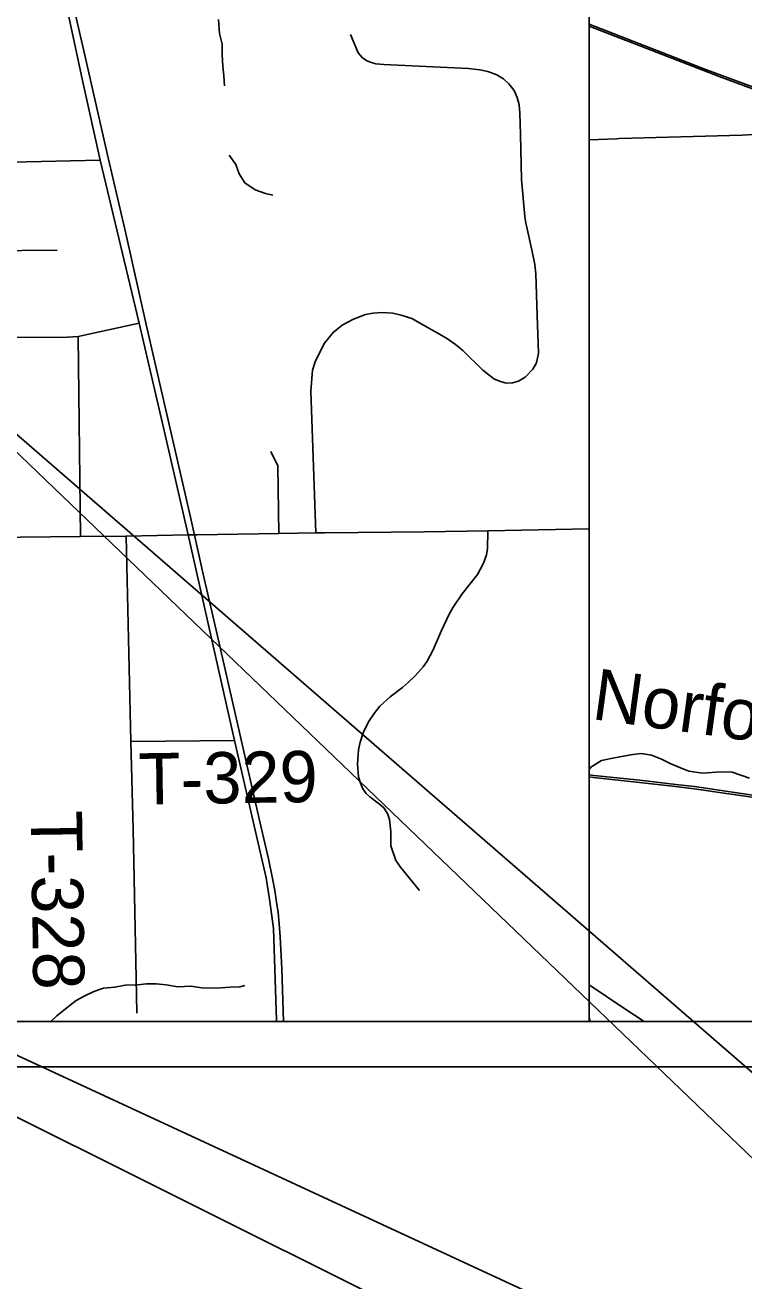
# Model space of a CAD drawing. Extents: x 25.6 to 80.6, y 0.2 to 24.5.
# Drawn here: x 43.163 to 44.756, y 13.756 to 16.537 of the extents above; entities that cross this region are included whole.
import ezdxf

# ---------------------------------------------------------------- set-up
doc = ezdxf.new("R2010")
doc.units = 0
for name, color, linetype in [('GM_X_County_Road', 7, 'Continuous'), ('GM_X_Minor_River', 7, 'Continuous'), ('GM_X_Rail_Line', 7, 'Continuous'), ('GM_X_Rail_Line_Text', 7, 'Continuous'), ('GM_X_State_Route', 7, 'Continuous'), ('GM_X_Township_Road', 7, 'Continuous'), ('GM_X_Township_Road_Text', 7, 'Continuous'), ('GM_X_US_Route', 7, 'Continuous'), ('SH_Data', 7, 'Continuous'), ('SH_Text', 7, 'Continuous')]:
    doc.layers.add(name, color=color, linetype=linetype)

msp = doc.modelspace()

# ---------------------------------------------------------------- linework, layer by layer
at = {"layer": 'GM_X_County_Road'}
for p, q in [((44.4128, 16.2831), (44.4744, 16.2855)), ((43.5241, 15.4082), (43.4744, 15.6231))]:
    msp.add_line(p, q, dxfattribs=at)
for points in [[(43.4744, 15.6231), (43.4157, 15.8771), (43.3295, 16.2378), (43.2913, 16.4079), (43.2182, 16.7492), (43.2068, 16.8496), (43.2038, 16.9808), (43.2018, 17.1076), (43.1983, 17.2332), (43.1967, 17.3603), (43.1924, 17.511), (43.1904, 17.6677), (43.19, 17.6872)], [(44.4744, 16.2855), (44.4803, 16.2858), (44.7518, 16.2938)], [(44.7518, 16.2938), (44.7637, 16.2941), (44.9482, 16.2948), (44.9691, 16.2966)], [(43.7204, 14.3303), (43.7203, 14.3334), (43.7134, 14.5361), (43.7054, 14.5964), (43.6968, 14.6488), (43.627, 14.9528), (43.5241, 15.4082)], [(44.5345, 14.3303), (44.4916, 14.3587), (44.4128, 14.4115)]]:
    msp.add_lwpolyline(points, dxfattribs=at)
at = {"layer": 'GM_X_Minor_River'}
for points in [[(43.5916, 16.5497), (43.5935, 16.5186), (43.5992, 16.4951), (43.5996, 16.4716), (43.6007, 16.4465), (43.6033, 16.4246), (43.6044, 16.4025)], [(43.615, 16.2493), (43.6297, 16.2282), (43.6369, 16.2078), (43.65, 16.1883), (43.673, 16.1726), (43.6959, 16.1646), (43.7118, 16.161)], [(44.7046, 14.8831), (44.6637, 14.8804), (44.634, 14.8847), (44.6149, 14.8921), (44.5921, 14.9017), (44.573, 14.9114), (44.5509, 14.9203), (44.5288, 14.9238), (44.5099, 14.9221), (44.4886, 14.9181), (44.4652, 14.914), (44.4402, 14.9085), (44.4168, 14.8938), (44.4128, 14.8885)], [(44.7046, 14.8831), (44.7297, 14.8827), (44.7487, 14.8762), (44.7685, 14.8696)], [(43.2198, 14.3303), (43.2331, 14.3431), (43.2526, 14.3586), (43.2758, 14.3772), (43.2953, 14.3873), (43.3149, 14.3967), (43.3367, 14.4046), (43.3617, 14.4064), (43.3844, 14.4106), (43.4124, 14.4117), (43.4321, 14.4135), (43.4533, 14.4138), (43.4753, 14.4118), (43.5011, 14.4069), (43.5306, 14.4088), (43.5534, 14.4053), (43.5731, 14.4041), (43.5966, 14.4051), (43.617, 14.4062), (43.639, 14.4073), (43.6496, 14.4104)]]:
    msp.add_lwpolyline(points, dxfattribs=at)
at = {"layer": 'GM_X_Rail_Line'}
for points in [[(43.7355, 14.3303), (43.7315, 14.4468), (43.7297, 14.4902), (43.7278, 14.5176), (43.726, 14.5466), (43.7237, 14.5715), (43.7203, 14.5945), (43.7161, 14.6203), (43.7114, 14.6473), (43.7025, 14.6906), (43.6834, 14.7698), (43.5909, 15.1777), (43.5577, 15.3212), (43.5292, 15.4472), (43.4312, 15.8739), (43.3858, 16.0756), (43.3445, 16.2531), (43.2951, 16.4705), (43.2554, 16.6435)], [(47.8128, 15.8191), (47.6057, 15.8302), (47.3402, 15.8521), (47.1631, 15.8871), (46.9912, 15.9223), (46.7273, 15.9853), (45.9383, 16.1769), (45.6136, 16.2567), (45.5036, 16.2842), (45.3992, 16.2924), (45.0499, 16.3176), (44.9789, 16.3252), (44.6728, 16.4383), (44.4128, 16.5397)], [(44.4128, 14.8771), (44.4231, 14.8756), (44.5249, 14.8648), (44.6048, 14.8557), (44.6465, 14.8507), (44.805, 14.8274), (45.0669, 14.7959), (45.2891, 14.7633), (46.0102, 14.6483), (46.3148, 14.5918), (46.4227, 14.5651), (46.528, 14.5372), (46.6857, 14.4857), (46.9234, 14.4078), (47.0403, 14.372), (47.1373, 14.3511), (47.2255, 14.3378), (47.2936, 14.3374), (47.3809, 14.3425), (47.4529, 14.3573), (47.553, 14.386), (47.7232, 14.4468), (47.8128, 14.4801)], [(44.4128, 14.8724), (44.4226, 14.871), (44.5243, 14.8601), (44.6043, 14.851), (44.6459, 14.846), (44.8044, 14.8227), (45.0663, 14.7912), (45.2884, 14.7586), (46.0094, 14.6437), (46.3138, 14.5872), (46.4216, 14.5606), (46.5266, 14.5327), (46.6843, 14.4812), (46.9219, 14.4033), (47.0391, 14.3674), (47.1365, 14.3464), (47.2252, 14.3331), (47.2937, 14.3327), (47.3816, 14.3378), (47.454, 14.3527), (47.5545, 14.3816), (47.7248, 14.4424), (47.8128, 14.4751)]]:
    msp.add_lwpolyline(points, dxfattribs=at)
at = {"layer": 'GM_X_State_Route'}
msp.add_lwpolyline([(44.4128, 16.5349), (44.7012, 16.4233), (44.9007, 16.3494), (45.0032, 16.3151), (45.0376, 16.3068), (45.0416, 16.3062)], dxfattribs=at)
at = {"layer": 'GM_X_Township_Road'}
for p, q in [((43.3295, 16.2378), (42.7101, 16.2251)), ((43.2803, 15.8476), (43.2853, 15.4047)), ((43.3968, 14.9504), (43.627, 14.9528)), ((44.4152, 14.3303), (44.4128, 14.3384))]:
    msp.add_line(p, q, dxfattribs=at)
for points in [[(44.2739, 16.093), (44.2726, 16.0987), (44.2706, 16.1135), (44.2631, 16.1953), (44.2606, 16.2947), (44.2595, 16.3421), (44.2578, 16.3606), (44.2532, 16.3768), (44.2463, 16.3921), (44.2345, 16.4075), (44.2228, 16.4184), (44.2084, 16.4272), (44.1883, 16.4347), (44.1707, 16.4384), (44.1451, 16.4412), (43.9579, 16.4499), (43.9401, 16.4516), (43.9303, 16.4548), (43.9201, 16.4583), (43.9096, 16.4652), (43.9009, 16.4756), (43.8837, 16.5167)], [(43.807, 15.4125), (43.7963, 15.7266), (43.7996, 15.7728), (43.8064, 15.7936), (43.8262, 15.8329), (43.8455, 15.8565), (43.8655, 15.8727), (43.8906, 15.8862), (43.9175, 15.8965), (43.9341, 15.8995), (43.9536, 15.9005), (43.9775, 15.8993), (43.9962, 15.8949), (44.0195, 15.8873), (44.0965, 15.8442), (44.1163, 15.8299), (44.1331, 15.8164), (44.1774, 15.7727), (44.1902, 15.7624), (44.2014, 15.7542), (44.2144, 15.749), (44.2287, 15.7444), (44.2427, 15.7447), (44.256, 15.7487), (44.2712, 15.7576), (44.2882, 15.7753), (44.2958, 15.7893), (44.3008, 15.8109), (44.2975, 15.8943), (44.2947, 15.9864), (44.2927, 16.0072), (44.2865, 16.0357), (44.2739, 16.093)], [(43.0737, 16.0369), (43.0757, 16.037), (43.2341, 16.039)], [(43.4157, 15.8771), (43.2803, 15.8476), (43.2569, 15.8464), (43.0785, 15.8456), (42.7196, 15.8403)], [(43.7248, 15.4112), (43.7226, 15.5612), (43.7074, 15.5932)], [(43.9661, 14.7909), (43.9577, 14.8035), (43.9485, 14.8116), (43.9271, 14.828), (43.9185, 14.8353), (43.9116, 14.8456), (43.906, 14.8586), (43.902, 14.8722), (43.8997, 14.9007), (43.902, 14.9321), (43.9053, 14.9491), (43.912, 14.9701), (43.9238, 14.994), (43.9361, 15.0128), (43.9493, 15.0288), (43.9722, 15.0493), (43.9992, 15.0703), (44.0124, 15.0818), (44.0273, 15.0958), (44.0449, 15.1157), (44.0541, 15.1285), (44.0671, 15.1533), (44.0858, 15.1966), (44.1027, 15.2325), (44.1111, 15.2482), (44.1317, 15.2775), (44.1654, 15.3203), (44.179, 15.3454), (44.1853, 15.3643), (44.1876, 15.3783), (44.188, 15.417)], [(43.4104, 14.349), (43.4088, 14.4266), (43.402, 14.7567), (43.3968, 14.9504), (43.3867, 15.4055)], [(44.0365, 14.6209), (43.9944, 14.6721), (43.9843, 14.6869), (43.9736, 14.7194), (43.9734, 14.7513), (43.9703, 14.7775), (43.9661, 14.7909)]]:
    msp.add_lwpolyline(points, dxfattribs=at)
at = {"layer": 'GM_X_US_Route'}
for p, q in [((43.827, 15.4128), (44.0476, 15.4153)), ((44.0476, 15.4153), (44.188, 15.417)), ((44.188, 15.417), (44.4128, 15.4218)), ((43.5241, 15.4082), (43.5442, 15.4085))]:
    msp.add_line(p, q, dxfattribs=at)
for points in [[(43.5442, 15.4085), (43.7248, 15.4112), (43.807, 15.4125), (43.827, 15.4128)], [(42.7264, 15.3972), (43.0843, 15.4023), (43.2853, 15.4047), (43.3867, 15.4055), (43.5241, 15.4082)]]:
    msp.add_lwpolyline(points, dxfattribs=at)
at = {"layer": 'SH_Data'}
for p, q in [((44.4128, 21.1303), (44.4128, 14.3303)), ((37.6128, 14.3303), (44.4128, 14.3303)), ((37.6128, 14.3303), (44.4128, 14.3303)), ((37.5128, 14.2303), (47.9128, 14.2303))]:
    msp.add_line(p, q, dxfattribs=at)
at = {"layer": 'SH_Text'}
for points in [[(37.6128, 21.1303), (44.4128, 21.1303), (44.4128, 14.3303), (37.6128, 14.3303)], [(37.6128, 21.1303), (44.4128, 21.1303), (44.4128, 14.3303), (37.6128, 14.3303)], [(41.0128, 14.3303), (44.4128, 14.3303), (44.4128, 17.7303), (41.0128, 17.7303)], [(41.0128, 14.3303), (44.4128, 14.3303), (44.4128, 17.7303), (41.0128, 17.7303)], [(44.4128, 14.3303), (47.8128, 14.3303), (47.8128, 17.7303), (44.4128, 17.7303)], [(44.9027, 13.4418), (44.9027, 13.2418), (39.3128, 16.0303)], [(44.8898, 14.1167), (44.8898, 13.9167), (42.7135, 16.0036)]]:
    msp.add_lwpolyline(points, close=True, dxfattribs=at)

# ---------------------------------------------------------------- texts
at = {"layer": 'GM_X_Rail_Line_Text'}
msp.add_text('Norfolk Southern', height=0.113258, rotation=352.1349, dxfattribs=at).set_placement((44.4163, 15.0006))
at = {"layer": 'GM_X_Township_Road_Text'}
for s, rotation, p in [('T-329', 0.8421, (43.4151, 14.8108)), ('T-328', 270.8431, (43.1754, 14.797))]:
    msp.add_text(s, height=0.11364, rotation=rotation, dxfattribs=at).set_placement(p)

doc.saveas('drawing.dxf')
